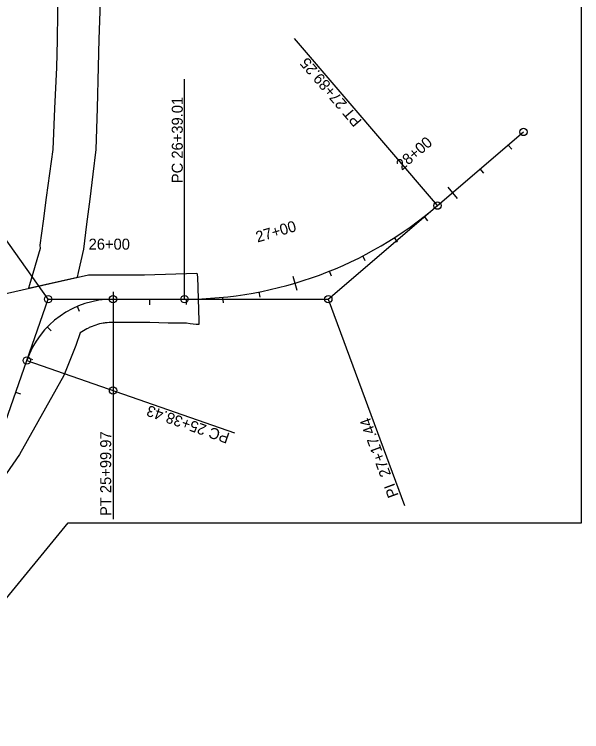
# Model space of a CAD drawing. Extents: x 1710723 to 1713003, y 548603 to 551142.
# Drawn here: x 1712442.1 to 1712751.6, y 549510.2 to 549901.4 of the extents above; entities that cross this region are included whole.
import ezdxf

# ---------------------------------------------------------------- set-up
doc = ezdxf.new("R2010")
doc.units = 0
for name, color, linetype in [('R_Horz Alg', 7, 'Continuous'), ('R_Horz Alg Annot', 7, 'Continuous'), ('R_MOT', 7, 'Continuous'), ('R_No Plot', 7, 'Continuous')]:
    doc.layers.add(name, color=color, linetype=linetype)

msp = doc.modelspace()

# ---------------------------------------------------------------- linework, layer by layer
at = {"layer": 'R_Horz Alg'}
for p, q in [((1712672.97, 549797.07), (1712719.88, 549837.24)), ((1712495.92, 549746.07), (1712534.97, 549746.07)), ((1712378.29, 549510.24), (1712448.88, 549712.66))]:
    msp.add_line(p, q, dxfattribs=at)
for centre, radius, start, end in [((1712534.97, 549958.28), 212.21, 270, 310.5648), ((1712495.92, 549696.25), 49.82, 90, 160.7734)]:
    msp.add_arc(centre, radius, start, end, dxfattribs=at)
at = {"layer": 'R_Horz Alg Annot'}
for p, q in [((1712613.39, 549746.07), (1712672.97, 549797.07)), ((1712448.88, 549712.66), (1712460.53, 549746.07)), ((1712460.53, 549746.07), (1712495.92, 549746.07)), ((1712534.97, 549746.07), (1712613.39, 549746.07))]:
    msp.add_line(p, q, dxfattribs=at)
for points in [[(1712672.97, 549797.07), (1712594.93, 549888.23)], [(1712534.97, 549746.07), (1712534.97, 549866.07)], [(1712460.53, 549746.07), (1712391.04, 549843.91)], [(1712713.47, 549827.8), (1712711.52, 549830.07)], [(1712698.27, 549814.79), (1712696.32, 549817.07)], [(1712678.53, 549807.1), (1712683.73, 549801.02)], [(1712667.66, 549788.85), (1712665.81, 549791.21)], [(1712651.12, 549777.11), (1712649.5, 549779.64)], [(1712633.56, 549766.99), (1712632.18, 549769.65)], [(1712593.98, 549758.61), (1712596.25, 549750.94)], [(1712615.12, 549758.56), (1712614, 549761.34)], [(1712495.95, 549750.07), (1712495.95, 549742.07)], [(1712556.22, 549744.13), (1712555.92, 549747.11)], [(1712576.27, 549747.08), (1712575.7, 549750.02)], [(1712495.92, 549746.07), (1712495.92, 549626.07)], [(1712515.95, 549743.07), (1712515.95, 549746.07)], [(1712535.97, 549743.08), (1712535.95, 549746.08)], [(1712613.39, 549746.07), (1712654.99, 549633.51)], [(1712477.65, 549739.36), (1712476.48, 549742.12)], [(1712462.26, 549728.8), (1712460.11, 549730.88)], [(1712448.88, 549712.66), (1712562.19, 549673.14)], [(1712452.22, 549713.06), (1712449.42, 549714.13)], [(1712445.64, 549694.27), (1712442.81, 549695.26)]]:
    msp.add_lwpolyline(points, dxfattribs=at)
for centre in [(1712719.88, 549837.24), (1712672.97, 549797.07), (1712460.53, 549746.07), (1712495.92, 549746.07), (1712534.97, 549746.07), (1712613.39, 549746.07), (1712448.88, 549712.66), (1712495.92, 549696.25)]:
    msp.add_circle(centre, 2, dxfattribs=at)
at = {"layer": 'R_MOT'}
for p, q in [((1712541.93, 549758.2), (1712542.76, 549734.21)), ((1712542.76, 549734.21), (1712542.74, 549732.27))]:
    msp.add_line(p, q, dxfattribs=at)
for points in [[(1712476.47, 549758.02), (1712477.05, 549760.53), (1712480.02, 549773.38), (1712481.71, 549786.98), (1712483.39, 549800.57), (1712485.08, 549814.16), (1712486.77, 549827.75), (1712487.4, 549850.22), (1712488.04, 549872.68), (1712488.45, 549887.86), (1712488.86, 549903.03), (1712489.27, 549918.2), (1712489.68, 549933.37), (1712489.85, 549948.48), (1712490.03, 549963.6), (1712490.2, 549978.71), (1712490.38, 549993.82), (1712493.07, 549996.49), (1712493.53, 550000.02), (1712492.77, 550002.31)], [(1712466.43, 549988.37), (1712467.17, 549983.23), (1712466.95, 549970.47), (1712466.73, 549957.72), (1712466.52, 549944.96), (1712466.3, 549932.21), (1712466, 549917.25), (1712465.71, 549902.29), (1712465.42, 549887.33), (1712465.12, 549872.38), (1712464.08, 549850.01), (1712463.03, 549827.64), (1712461.26, 549814.62), (1712459.5, 549801.6), (1712457.73, 549788.58), (1712455.96, 549775.56), (1712456.16, 549773.79), (1712450.41, 549753.98), (1712449.78, 549752)], [(1712436.73, 549749.05), (1712482.53, 549759.39), (1712513.12, 549759.39), (1712541.71, 549760.22), (1712541.93, 549758.2)], [(1712449.78, 549752), (1712476.47, 549758.02)], [(1712542.74, 549732.27), (1712541.24, 549732.29), (1712538.1, 549732.67), (1712536.01, 549732.96), (1712534.97, 549733.02), (1712525.95, 549732.9), (1712520.95, 549733.08), (1712515.95, 549733.27), (1712505.95, 549733.36), (1712497.71, 549733.34), (1712495.95, 549733.33), (1712495.92, 549733.33), (1712494.86, 549733.32), (1712493.8, 549733.27), (1712492.73, 549733.19), (1712491.67, 549733.08), (1712491.1, 549733), (1712490.76, 549732.95), (1712490.65, 549732.94), (1712490.62, 549732.93), (1712490.48, 549732.91), (1712489.57, 549732.75), (1712488.56, 549732.55), (1712488.53, 549732.54), (1712487.5, 549732.26), (1712486.49, 549731.95), (1712485.48, 549731.6), (1712484.49, 549731.21), (1712483.52, 549730.79), (1712482.98, 549730.54), (1712482.57, 549730.34), (1712481.67, 549729.88), (1712481.63, 549729.86), (1712480.71, 549729.34), (1712479.82, 549728.8), (1712478.92, 549728.25), (1712478.07, 549727.7)], [(1712478.07, 549727.7), (1712475.64, 549720.74), (1712469.03, 549704.48), (1712444.83, 549661.33), (1712417.63, 549622.18), (1712370.31, 549569.49), (1712361.6, 549562.59)]]:
    msp.add_lwpolyline(points, dxfattribs=at)
at = {"layer": 'R_No Plot'}
msp.add_line((1712429.32, 549572.87), (1712471.46, 549624.18), dxfattribs=at)
msp.add_lwpolyline([(1712471.46, 549624.18), (1712751.62, 549624.18), (1712751.62, 549942.65), (1712636.33, 549942.65)], dxfattribs=at)

# ---------------------------------------------------------------- texts
at = {"layer": 'R_Horz Alg Annot'}
for s, rotation, p in [('PT 27+89.25', 130.5648, (1712632.05, 549843.33)), ('PC 26+39.01', 90, (1712533.97, 549809.33)), ('28+00', 40.5648, (1712653.54, 549815.99)), ('27+00', 16.4663, (1712574.8, 549776.93)), ('PC 25+38.43', 160.7734, (1712560.03, 549672.84)), ('PI  27+17.44', 110.2824, (1712651.86, 549639.11)), ('PT 25+99.97', 90, (1712494.92, 549627.82))]:
    msp.add_text(s, height=6, rotation=rotation, dxfattribs=at).set_placement(p)
msp.add_text('26+00', height=6, dxfattribs=at).set_placement((1712482.61, 549773.07))

doc.saveas('drawing.dxf')
